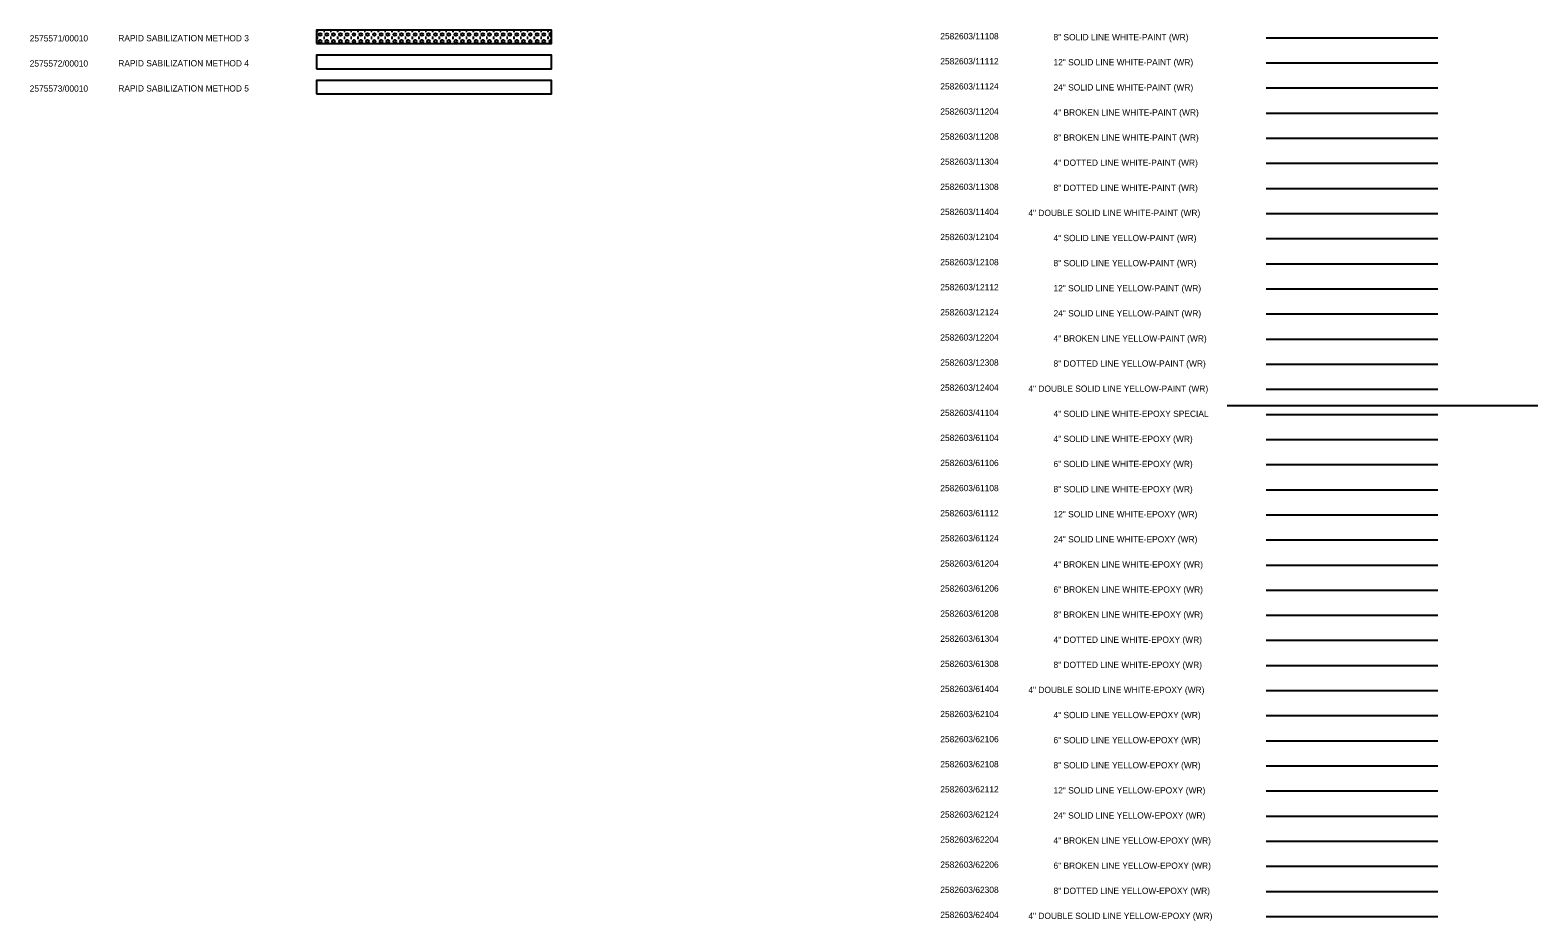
# Model space of a CAD drawing. Extents: x 2147716 to 2176321, y 2125040 to 2131750.
# Drawn here: x 2155113 to 2156914, y 2125731 to 2126795 of the extents above; entities that cross this region are included whole.
import ezdxf

# ---------------------------------------------------------------- set-up
doc = ezdxf.new("R2010")
doc.units = 0
for name, color, linetype in [('ALI RD INP', 7, 'Continuous'), ('DETAIL TXT', 7, 'Continuous'), ('PVMT STRP', 7, 'Continuous'), ('TURF EST', 7, 'Continuous')]:
    doc.layers.add(name, color=color, linetype=linetype)

msp = doc.modelspace()

# ---------------------------------------------------------------- linework, layer by layer
at = {"layer": 'ALI RD INP'}
for p, q in [((2155455.1, 2126794.9), (2155456.8, 2126794.9)), ((2155455.1, 2126794), (2155456.8, 2126794)), ((2155455.1, 2126786.7), (2155456.8, 2126786.7)), ((2155455.1, 2126785.8), (2155456.8, 2126785.8)), ((2155463.1, 2126794.9), (2155464.9, 2126794.9)), ((2155463.1, 2126794), (2155464.9, 2126794)), ((2155463.1, 2126786.7), (2155464.9, 2126786.7)), ((2155463.1, 2126785.8), (2155464.9, 2126785.8)), ((2155471.2, 2126794.9), (2155473, 2126794.9)), ((2155471.2, 2126794), (2155473, 2126794)), ((2155471.2, 2126786.7), (2155473, 2126786.7)), ((2155471.2, 2126785.8), (2155473, 2126785.8)), ((2155479.3, 2126794.9), (2155481.1, 2126794.9)), ((2155479.3, 2126794), (2155481.1, 2126794)), ((2155479.3, 2126786.7), (2155481.1, 2126786.7)), ((2155479.3, 2126785.8), (2155481.1, 2126785.8)), ((2155487.4, 2126794.9), (2155489.2, 2126794.9)), ((2155487.4, 2126794), (2155489.2, 2126794)), ((2155487.4, 2126786.7), (2155489.2, 2126786.7)), ((2155487.4, 2126785.8), (2155489.2, 2126785.8)), ((2155495.5, 2126794.9), (2155497.3, 2126794.9)), ((2155495.5, 2126794), (2155497.3, 2126794)), ((2155495.5, 2126786.7), (2155497.3, 2126786.7)), ((2155495.5, 2126785.8), (2155497.3, 2126785.8)), ((2155503.6, 2126794.9), (2155505.4, 2126794.9)), ((2155503.6, 2126794), (2155505.4, 2126794)), ((2155503.6, 2126786.7), (2155505.4, 2126786.7)), ((2155503.6, 2126785.8), (2155505.4, 2126785.8)), ((2155511.7, 2126794.9), (2155513.5, 2126794.9)), ((2155511.7, 2126794), (2155513.5, 2126794)), ((2155511.7, 2126786.7), (2155513.5, 2126786.7)), ((2155511.7, 2126785.8), (2155513.5, 2126785.8)), ((2155519.8, 2126794.9), (2155521.6, 2126794.9)), ((2155519.8, 2126794), (2155521.6, 2126794)), ((2155519.8, 2126786.7), (2155521.6, 2126786.7)), ((2155519.8, 2126785.8), (2155521.6, 2126785.8)), ((2155527.9, 2126794.9), (2155529.7, 2126794.9)), ((2155527.9, 2126794), (2155529.7, 2126794)), ((2155527.9, 2126786.7), (2155529.7, 2126786.7)), ((2155527.9, 2126785.8), (2155529.7, 2126785.8)), ((2155536, 2126794.9), (2155537.8, 2126794.9)), ((2155536, 2126794), (2155537.8, 2126794)), ((2155536, 2126786.7), (2155537.8, 2126786.7)), ((2155536, 2126785.8), (2155537.8, 2126785.8)), ((2155544.1, 2126794.9), (2155545.9, 2126794.9)), ((2155544.1, 2126794), (2155545.9, 2126794)), ((2155544.1, 2126786.7), (2155545.9, 2126786.7)), ((2155544.1, 2126785.8), (2155545.9, 2126785.8)), ((2155552.2, 2126794.9), (2155554, 2126794.9)), ((2155552.2, 2126794), (2155554, 2126794)), ((2155552.2, 2126786.7), (2155554, 2126786.7)), ((2155552.2, 2126785.8), (2155554, 2126785.8)), ((2155560.3, 2126794.9), (2155562.1, 2126794.9)), ((2155560.3, 2126794), (2155562.1, 2126794)), ((2155560.3, 2126786.7), (2155562.1, 2126786.7)), ((2155560.3, 2126785.8), (2155562.1, 2126785.8)), ((2155568.4, 2126794.9), (2155570.2, 2126794.9)), ((2155568.4, 2126794), (2155570.2, 2126794)), ((2155568.4, 2126786.7), (2155570.2, 2126786.7)), ((2155568.4, 2126785.8), (2155570.2, 2126785.8)), ((2155576.5, 2126794.9), (2155578.3, 2126794.9)), ((2155576.5, 2126794), (2155578.3, 2126794)), ((2155576.5, 2126786.7), (2155578.3, 2126786.7)), ((2155576.5, 2126785.8), (2155578.3, 2126785.8)), ((2155584.6, 2126794.9), (2155586.4, 2126794.9)), ((2155584.6, 2126794), (2155586.4, 2126794)), ((2155584.6, 2126786.7), (2155586.4, 2126786.7)), ((2155584.6, 2126785.8), (2155586.4, 2126785.8)), ((2155592.7, 2126794.9), (2155594.5, 2126794.9)), ((2155592.7, 2126794), (2155594.5, 2126794)), ((2155592.7, 2126786.7), (2155594.5, 2126786.7)), ((2155592.7, 2126785.8), (2155594.5, 2126785.8)), ((2155600.8, 2126794.9), (2155602.6, 2126794.9)), ((2155600.8, 2126794), (2155602.6, 2126794)), ((2155600.8, 2126786.7), (2155602.6, 2126786.7)), ((2155600.8, 2126785.8), (2155602.6, 2126785.8)), ((2155608.9, 2126794.9), (2155610.7, 2126794.9)), ((2155608.9, 2126794), (2155610.7, 2126794)), ((2155608.9, 2126786.7), (2155610.7, 2126786.7)), ((2155608.9, 2126785.8), (2155610.7, 2126785.8)), ((2155617, 2126794.9), (2155618.8, 2126794.9)), ((2155617, 2126794), (2155618.8, 2126794)), ((2155617, 2126786.7), (2155618.8, 2126786.7)), ((2155617, 2126785.8), (2155618.8, 2126785.8)), ((2155625.1, 2126794.9), (2155626.9, 2126794.9)), ((2155625.1, 2126794), (2155626.9, 2126794)), ((2155625.1, 2126786.7), (2155626.9, 2126786.7)), ((2155625.1, 2126785.8), (2155626.9, 2126785.8)), ((2155633.2, 2126794.9), (2155635, 2126794.9)), ((2155633.2, 2126794), (2155635, 2126794)), ((2155633.2, 2126786.7), (2155635, 2126786.7)), ((2155633.2, 2126785.8), (2155635, 2126785.8)), ((2155641.3, 2126794.9), (2155643.1, 2126794.9)), ((2155641.3, 2126794), (2155643.1, 2126794)), ((2155641.3, 2126786.7), (2155643.1, 2126786.7)), ((2155641.3, 2126785.8), (2155643.1, 2126785.8)), ((2155649.4, 2126794.9), (2155651.2, 2126794.9)), ((2155649.4, 2126794), (2155651.2, 2126794)), ((2155649.4, 2126786.7), (2155651.2, 2126786.7)), ((2155649.4, 2126785.8), (2155651.2, 2126785.8)), ((2155657.5, 2126794.9), (2155659.3, 2126794.9)), ((2155657.5, 2126794), (2155659.3, 2126794)), ((2155657.5, 2126786.7), (2155659.3, 2126786.7)), ((2155657.5, 2126785.8), (2155659.3, 2126785.8)), ((2155665.6, 2126794.9), (2155667.4, 2126794.9)), ((2155665.6, 2126794), (2155667.4, 2126794)), ((2155665.6, 2126786.7), (2155667.4, 2126786.7)), ((2155665.6, 2126785.8), (2155667.4, 2126785.8)), ((2155673.7, 2126794.9), (2155675.5, 2126794.9)), ((2155673.7, 2126794), (2155675.5, 2126794)), ((2155673.7, 2126786.7), (2155675.5, 2126786.7)), ((2155673.7, 2126785.8), (2155675.5, 2126785.8)), ((2155681.8, 2126794.9), (2155683.6, 2126794.9)), ((2155681.8, 2126794), (2155683.6, 2126794)), ((2155681.8, 2126786.7), (2155683.6, 2126786.7)), ((2155681.8, 2126785.8), (2155683.6, 2126785.8)), ((2155689.9, 2126794.9), (2155691.7, 2126794.9)), ((2155689.9, 2126794), (2155691.7, 2126794)), ((2155689.9, 2126786.7), (2155691.7, 2126786.7)), ((2155689.9, 2126785.8), (2155691.7, 2126785.8)), ((2155698, 2126794.9), (2155699.8, 2126794.9)), ((2155698, 2126794), (2155699.8, 2126794)), ((2155698, 2126786.7), (2155699.8, 2126786.7)), ((2155698, 2126785.8), (2155699.8, 2126785.8)), ((2155706.1, 2126794.9), (2155707.9, 2126794.9)), ((2155706.1, 2126794), (2155707.9, 2126794)), ((2155706.1, 2126786.7), (2155707.9, 2126786.7)), ((2155706.1, 2126785.8), (2155707.9, 2126785.8)), ((2155714.2, 2126794.9), (2155716, 2126794.9)), ((2155714.2, 2126794), (2155716, 2126794)), ((2155714.2, 2126786.7), (2155716, 2126786.7)), ((2155714.2, 2126785.8), (2155716, 2126785.8)), ((2155722.3, 2126794.9), (2155724.1, 2126794.9)), ((2155722.3, 2126794), (2155724.1, 2126794)), ((2155722.3, 2126786.7), (2155724.1, 2126786.7)), ((2155722.3, 2126785.8), (2155724.1, 2126785.8)), ((2155730.4, 2126794.9), (2155732.2, 2126794.9)), ((2155730.4, 2126794), (2155732.2, 2126794)), ((2155730.4, 2126786.7), (2155732.2, 2126786.7)), ((2155730.4, 2126785.8), (2155732.2, 2126785.8))]:
    msp.add_line(p, q, dxfattribs=at)
for centre in [(2155459.2, 2126790), (2155459.2, 2126781.8), (2155467.3, 2126790), (2155467.3, 2126781.8), (2155475.4, 2126790), (2155475.4, 2126781.8), (2155483.5, 2126790), (2155483.5, 2126781.8), (2155491.6, 2126790), (2155491.6, 2126781.8), (2155499.7, 2126790), (2155499.7, 2126781.8), (2155507.8, 2126790), (2155507.8, 2126781.8), (2155515.9, 2126790), (2155515.9, 2126781.8), (2155524, 2126790), (2155524, 2126781.8), (2155532.1, 2126790), (2155532.1, 2126781.8), (2155540.2, 2126790), (2155540.2, 2126781.8), (2155548.3, 2126790), (2155548.3, 2126781.8), (2155556.4, 2126790), (2155556.4, 2126781.8), (2155564.5, 2126790), (2155564.5, 2126781.8), (2155572.6, 2126790), (2155572.6, 2126781.8), (2155580.7, 2126790), (2155580.7, 2126781.8), (2155588.8, 2126790), (2155588.8, 2126781.8), (2155596.9, 2126790), (2155596.9, 2126781.8), (2155605, 2126790), (2155605, 2126781.8), (2155613.1, 2126790), (2155613.1, 2126781.8), (2155621.2, 2126790), (2155621.2, 2126781.8), (2155629.3, 2126790), (2155629.3, 2126781.8), (2155637.4, 2126790), (2155637.4, 2126781.8), (2155645.5, 2126790), (2155645.5, 2126781.8), (2155653.6, 2126790), (2155653.6, 2126781.8), (2155661.7, 2126790), (2155661.7, 2126781.8), (2155669.8, 2126790), (2155669.8, 2126781.8), (2155677.9, 2126790), (2155677.9, 2126781.8), (2155686, 2126790), (2155686, 2126781.8), (2155694.1, 2126790), (2155694.1, 2126781.8), (2155702.2, 2126790), (2155702.2, 2126781.8), (2155710.3, 2126790), (2155710.3, 2126781.8), (2155718.4, 2126790), (2155718.4, 2126781.8), (2155726.5, 2126790), (2155726.5, 2126781.8)]:
    msp.add_circle(centre, 1.67, dxfattribs=at)
for centre in [(2155734.6, 2126790), (2155734.6, 2126781.8)]:
    msp.add_arc(centre, 1.67, 49.2946, 310.7054, dxfattribs=at)
at = {"layer": 'DETAIL TXT'}
msp.add_line((2156542.5, 2126346.9), (2156913.6, 2126346.9), dxfattribs=at)
at = {"layer": 'PVMT STRP'}
for p, q in [((2156589.1, 2126786.1), (2156794.3, 2126786.1)), ((2156589.1, 2126756.1), (2156794.3, 2126756.1)), ((2156589.1, 2126726.1), (2156794.3, 2126726.1)), ((2156589.1, 2126696.1), (2156794.3, 2126696.1)), ((2156589.1, 2126666.1), (2156794.3, 2126666.1)), ((2156589.1, 2126636.1), (2156794.3, 2126636.1)), ((2156589.1, 2126606.1), (2156794.3, 2126606.1)), ((2156589.1, 2126576.1), (2156794.3, 2126576.1)), ((2156589.1, 2126546.1), (2156794.3, 2126546.1)), ((2156589.1, 2126516.1), (2156794.3, 2126516.1)), ((2156589.1, 2126486.1), (2156794.3, 2126486.1)), ((2156589.1, 2126456.1), (2156794.3, 2126456.1)), ((2156589.1, 2126426.1), (2156794.3, 2126426.1)), ((2156589.1, 2126396.1), (2156794.3, 2126396.1)), ((2156589.1, 2126366.1), (2156794.3, 2126366.1)), ((2156589.1, 2126336.1), (2156794.3, 2126336.1)), ((2156589.1, 2126306.1), (2156794.3, 2126306.1)), ((2156589.1, 2126276.1), (2156794.3, 2126276.1)), ((2156589.1, 2126246.1), (2156794.3, 2126246.1)), ((2156589.1, 2126216.1), (2156794.3, 2126216.1)), ((2156589.1, 2126186.1), (2156794.3, 2126186.1)), ((2156589.1, 2126156.1), (2156794.3, 2126156.1)), ((2156589.1, 2126126.1), (2156794.3, 2126126.1)), ((2156589.1, 2126096.1), (2156794.3, 2126096.1)), ((2156589.1, 2126066.1), (2156794.3, 2126066.1)), ((2156589.1, 2126036.1), (2156794.3, 2126036.1)), ((2156589.1, 2126006.1), (2156794.3, 2126006.1)), ((2156589.1, 2125976.1), (2156794.3, 2125976.1)), ((2156589.1, 2125946.1), (2156794.3, 2125946.1)), ((2156589.1, 2125916.1), (2156794.3, 2125916.1)), ((2156589.1, 2125886.1), (2156794.3, 2125886.1)), ((2156589.1, 2125856.1), (2156794.3, 2125856.1)), ((2156589.1, 2125826.1), (2156794.3, 2125826.1)), ((2156589.1, 2125796.1), (2156794.3, 2125796.1)), ((2156589.1, 2125766.1), (2156794.3, 2125766.1)), ((2156589.1, 2125736.1), (2156794.3, 2125736.1))]:
    msp.add_line(p, q, dxfattribs=at)
at = {"layer": 'TURF EST'}
for points in [[(2155455.1, 2126779.1), (2155735.7, 2126779.1), (2155735.7, 2126795.2), (2155455.1, 2126795.2)], [(2155455.1, 2126749.1), (2155735.7, 2126749.1), (2155735.7, 2126765.2), (2155455.1, 2126765.2)], [(2155455.1, 2126719.1), (2155735.7, 2126719.1), (2155735.7, 2126735.2), (2155455.1, 2126735.2)]]:
    msp.add_lwpolyline(points, close=True, dxfattribs=at)

# ---------------------------------------------------------------- texts
at = {"layer": 'DETAIL TXT'}
for s, p in [('2575571/00010', (2155112.4, 2126781.7)), ('RAPID SABILIZATION METHOD 3', (2155218.2, 2126781.9)), ('2582603/11108', (2156199.9, 2126784.3)), ('8" SOLID LINE WHITE-PAINT (WR)', (2156335.1, 2126783.1)), ('2575572/00010', (2155112.4, 2126751.7)), ('RAPID SABILIZATION METHOD 4', (2155218.2, 2126751.9)), ('2582603/11112', (2156199.9, 2126754.3)), ('12" SOLID LINE WHITE-PAINT (WR)', (2156335.1, 2126753.1)), ('2575573/00010', (2155112.4, 2126721.7)), ('RAPID SABILIZATION METHOD 5', (2155218.2, 2126721.9)), ('2582603/11124', (2156199.9, 2126724.3)), ('24" SOLID LINE WHITE-PAINT (WR)', (2156335.1, 2126723.1)), ('2582603/11204', (2156199.9, 2126694.3)), ('4" BROKEN LINE WHITE-PAINT (WR)', (2156335.1, 2126693.1)), ('2582603/11208', (2156199.9, 2126664.3)), ('8" BROKEN LINE WHITE-PAINT (WR)', (2156335.1, 2126663.1)), ('2582603/11304', (2156199.9, 2126634.3)), ('4" DOTTED LINE WHITE-PAINT (WR)', (2156335.1, 2126633.1)), ('2582603/11308', (2156199.9, 2126604.3)), ('8" DOTTED LINE WHITE-PAINT (WR)', (2156335.1, 2126603.1)), ('2582603/11404', (2156199.9, 2126574.3)), ('4" DOUBLE SOLID LINE WHITE-PAINT (WR)', (2156305.1, 2126573.1)), ('2582603/12104', (2156199.9, 2126544.3)), ('4" SOLID LINE YELLOW-PAINT (WR)', (2156335.1, 2126543.1)), ('2582603/12108', (2156199.9, 2126514.3)), ('8" SOLID LINE YELLOW-PAINT (WR)', (2156335.1, 2126513.1)), ('2582603/12112', (2156199.9, 2126484.3)), ('12" SOLID LINE YELLOW-PAINT (WR)', (2156335.1, 2126483.1)), ('2582603/12124', (2156199.9, 2126454.3)), ('24" SOLID LINE YELLOW-PAINT (WR)', (2156335.1, 2126453.1)), ('2582603/12204', (2156199.9, 2126424.3)), ('4" BROKEN LINE YELLOW-PAINT (WR)', (2156335.1, 2126423.1)), ('2582603/12308', (2156199.9, 2126394.3)), ('8" DOTTED LINE YELLOW-PAINT (WR)', (2156335.1, 2126393.1)), ('2582603/12404', (2156199.9, 2126364.3)), ('4" DOUBLE SOLID LINE YELLOW-PAINT (WR)', (2156305.1, 2126363.1)), ('2582603/41104', (2156199.9, 2126334.3)), ('4" SOLID LINE WHITE-EPOXY SPECIAL', (2156335.1, 2126333.1)), ('2582603/61104', (2156199.9, 2126304.3)), ('4" SOLID LINE WHITE-EPOXY (WR)', (2156335.1, 2126303.1)), ('2582603/61106', (2156199.9, 2126274.3)), ('6" SOLID LINE WHITE-EPOXY (WR)', (2156335.1, 2126273.1)), ('2582603/61108', (2156199.9, 2126244.3)), ('8" SOLID LINE WHITE-EPOXY (WR)', (2156335.1, 2126243.1)), ('2582603/61112', (2156199.9, 2126214.3)), ('12" SOLID LINE WHITE-EPOXY (WR)', (2156335.1, 2126213.1)), ('2582603/61124', (2156199.9, 2126184.3)), ('24" SOLID LINE WHITE-EPOXY (WR)', (2156335.1, 2126183.1)), ('2582603/61204', (2156199.9, 2126154.3)), ('4" BROKEN LINE WHITE-EPOXY (WR)', (2156335.1, 2126153.1)), ('2582603/61206', (2156199.9, 2126124.3)), ('6" BROKEN LINE WHITE-EPOXY (WR)', (2156335.1, 2126123.1)), ('2582603/61208', (2156199.9, 2126094.3)), ('8" BROKEN LINE WHITE-EPOXY (WR)', (2156335.1, 2126093.1)), ('2582603/61304', (2156199.9, 2126064.3)), ('4" DOTTED LINE WHITE-EPOXY (WR)', (2156335.1, 2126063.1)), ('2582603/61308', (2156199.9, 2126034.3)), ('8" DOTTED LINE WHITE-EPOXY (WR)', (2156335.1, 2126033.1)), ('2582603/61404', (2156199.9, 2126004.3)), ('4" DOUBLE SOLID LINE WHITE-EPOXY (WR)', (2156305.1, 2126003.1)), ('2582603/62104', (2156199.9, 2125974.3)), ('4" SOLID LINE YELLOW-EPOXY (WR)', (2156335.1, 2125973.1)), ('2582603/62106', (2156199.9, 2125944.3)), ('6" SOLID LINE YELLOW-EPOXY (WR)', (2156335.1, 2125943.1)), ('2582603/62108', (2156199.9, 2125914.3)), ('8" SOLID LINE YELLOW-EPOXY (WR)', (2156335.1, 2125913.1)), ('2582603/62112', (2156199.9, 2125884.3)), ('12" SOLID LINE YELLOW-EPOXY (WR)', (2156335.1, 2125883.1)), ('2582603/62124', (2156199.9, 2125854.3)), ('24" SOLID LINE YELLOW-EPOXY (WR)', (2156335.1, 2125853.1)), ('2582603/62204', (2156199.9, 2125824.3)), ('4" BROKEN LINE YELLOW-EPOXY (WR)', (2156335.1, 2125823.1)), ('2582603/62206', (2156199.9, 2125794.3)), ('6" BROKEN LINE YELLOW-EPOXY (WR)', (2156335.1, 2125793.1)), ('2582603/62308', (2156199.9, 2125764.3)), ('8" DOTTED LINE YELLOW-EPOXY (WR)', (2156335.1, 2125763.1)), ('2582603/62404', (2156199.9, 2125734.3)), ('4" DOUBLE SOLID LINE YELLOW-EPOXY (WR)', (2156305.1, 2125733.1))]:
    msp.add_text(s, height=7.5, dxfattribs=at).set_placement(p)

doc.saveas('drawing.dxf')
